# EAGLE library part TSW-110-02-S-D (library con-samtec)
THROUGH-HOLE .025" SQ POST HEADER Source: Samtec TSW.pdf
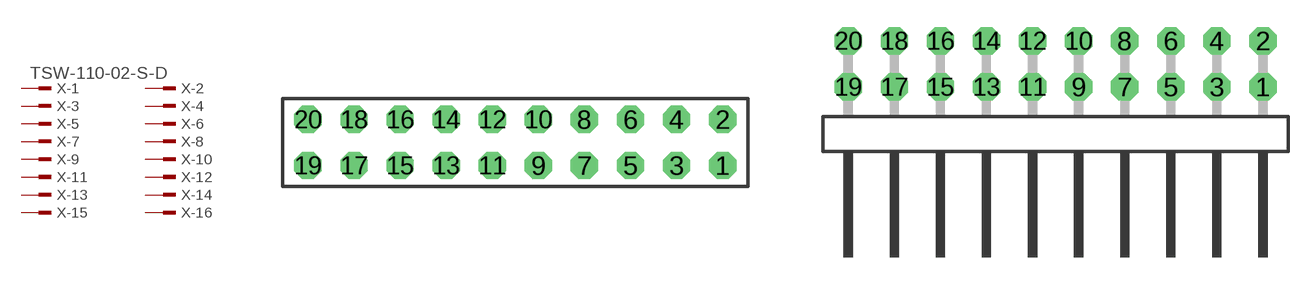
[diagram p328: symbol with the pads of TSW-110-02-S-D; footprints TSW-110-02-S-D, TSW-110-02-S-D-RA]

Designator prefix X; gates -1=MPINV -2=MPIN -3=MPIN -4=MPIN -5=MPIN -6=MPIN -7=MPIN -8=MPIN -9=MPIN -10=MPIN -11=MPIN -12=MPIN -13=MPIN -14=MPIN -15=MPIN -16=MPIN -17=MPIN -18=MPIN -19=MPIN -20=MPIN

## TSW-110-02-S-D (OC_FARNELL: unknown; OC_NEWARK: unknown)  [TSW-110-02-S-D]
1  -1:1  pas
2  -2:1  pas
3  -3:1  pas
4  -4:1  pas
5  -5:1  pas
6  -6:1  pas
7  -7:1  pas
8  -8:1  pas
9  -9:1  pas
10  -10:1  pas
11  -11:1  pas
12  -12:1  pas
13  -13:1  pas
14  -14:1  pas
15  -15:1  pas
16  -16:1  pas
17  -17:1  pas
18  -18:1  pas
19  -19:1  pas
20  -20:1  pas

## TSW-110-02-S-D-RA (OC_FARNELL: unknown; OC_NEWARK: unknown)  [TSW-110-02-S-D-RA]
Pads as for TSW-110-02-S-D

## Footprint TSW-110-02-S-D (pad centres in mm)
THROUGH-HOLE .025" SQ POST HEADER Source: Samtec TSW.pdf
drill 1 pad 1.5 octagon: 1 11.43,-1.27; 2 11.43,1.27; 3 8.89,-1.27; 4 8.89,1.27; 5 6.35,-1.27; 6 6.35,1.27; 7 3.81,-1.27; 8 3.81,1.27; 9 1.27,-1.27; 10 1.27,1.27; 11 -1.27,-1.27; 12 -1.27,1.27; 13 -3.81,-1.27; 14 -3.81,1.27; 15 -6.35,-1.27; 16 -6.35,1.27; 17 -8.89,-1.27; 18 -8.89,1.27; 19 -11.43,-1.27; 20 -11.43,1.27

## Footprint TSW-110-02-S-D-RA (pad centres in mm)
THROUGH-HOLE .025" SQ POST HEADER Source: Samtec TSW.pdf
drill 1 pad 1.5 octagon: 1 11.43,1.524; 2 11.43,4.064; 3 8.89,1.524; 4 8.89,4.064; 5 6.35,1.524; 6 6.35,4.064; 7 3.81,1.524; 8 3.81,4.064; 9 1.27,1.524; 10 1.27,4.064; 11 -1.27,1.524; 12 -1.27,4.064; 13 -3.81,1.524; 14 -3.81,4.064; 15 -6.35,1.524; 16 -6.35,4.064; 17 -8.89,1.524; 18 -8.89,4.064; 19 -11.43,1.524; 20 -11.43,4.064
